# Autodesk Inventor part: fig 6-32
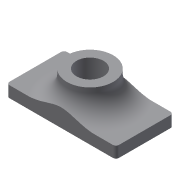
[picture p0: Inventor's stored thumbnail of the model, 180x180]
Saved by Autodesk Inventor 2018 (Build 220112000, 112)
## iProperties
Created: 2004-05
Part Number: fig 6-32
Document SubType Name: Modeling
Designer: CADCIM Technologies
Manufacturer: Standard
Standards Organization: Custom
Density: 1 g/cm^3
Material: Generic
Appearance: Default
Author: CADCIM Technologies
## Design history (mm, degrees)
sketch "Sketch1"
  geometry: L1 (-39.276, -18.692)-(33.721, -18.692); L2 (33.721, -18.692)-(33.721, 19.728); L3 (33.721, 19.728)-(-39.276, 19.728); L4 (-39.276, 19.728)-(-39.276, -18.692)
  constraints: 8 end point, 2 parallel, 1 horizontal, 1 perpendicular
extrude "Extrusion1" new body sketch "Sketch1" distance "d0" = 7.5; taper "d1" = 0 deg
fillet "Fillet1" dims "d2" = 2
sketch "Sketch2"
  geometry: C1 r 15.456 at (-2.778, 0.518)
  constraints: 1 centre point
extrude "Extrusion2" join sketch "Sketch2" distance "d3" = 17.25; taper "d4" = 0 deg
hole "Hole1" diameter "d8" = 18; stored, may be unused: countersink angle "d12" = 90 deg, drill point angle "d14" = 118 deg; dims "d6" = 10, "d7" = 10, "d9" = 6, "d10" = 4, "d11" = 2, "d13" = 8
fillet "Fillet2" dims "d5" = 14
body "Solid1"
